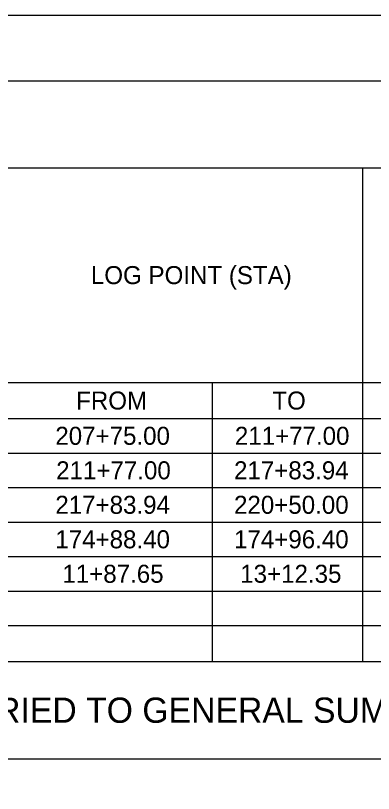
# Model space of a CAD drawing. Extents: x 0 to 53.1, y -5.3 to 22.
# Drawn here: x 5.19 to 7.93, y 16.05 to 22 of the extents above; entities that cross this region are included whole.
import ezdxf

# ---------------------------------------------------------------- set-up
doc = ezdxf.new("R2010")
doc.units = 0
for name, color, linetype in [('SH_Border', 7, 'Continuous'), ('SH_Cut_Line', 7, 'Continuous'), ('SH_Text', 7, 'Continuous')]:
    doc.layers.add(name, color=color, linetype=linetype)

msp = doc.modelspace()

# ---------------------------------------------------------------- linework, layer by layer
at = {"layer": 'SH_Border'}
msp.add_lwpolyline([(1.5, 21.5), (33.5, 21.5), (33.5, 0.5), (1.5, 0.5)], close=True, dxfattribs=at)
at = {"layer": 'SH_Cut_Line'}
msp.add_lwpolyline([(0, 0), (34, 0), (34, 22), (0, 22)], close=True, dxfattribs=at)
at = {"layer": 'SH_Text'}
for p, q in [((1.8384, 20.8354), (7.8504, 20.8354)), ((7.8504, 20.8354), (30.4824, 20.8354)), ((7.8504, 20.8354), (7.8504, 20.0194)), ((7.8504, 20.0194), (7.8504, 19.4674)), ((7.8504, 19.4674), (7.8504, 19.1914)), ((5.1144, 19.1914), (7.8504, 19.1914)), ((6.6984, 19.1914), (6.6984, 17.8594)), ((7.8504, 19.1914), (27.6024, 19.1914)), ((7.8504, 19.1914), (7.8504, 17.8594)), ((1.8384, 18.9154), (7.8504, 18.9154)), ((7.8504, 18.9154), (30.4824, 18.9154)), ((1.8384, 18.6514), (7.8504, 18.6514)), ((7.8504, 18.6514), (30.4824, 18.6514)), ((1.8384, 18.3874), (7.8504, 18.3874)), ((7.8504, 18.3874), (30.4824, 18.3874)), ((1.8384, 18.1234), (7.8504, 18.1234)), ((7.8504, 18.1234), (30.4824, 18.1234)), ((1.8384, 17.8594), (7.8504, 17.8594)), ((6.6984, 17.8594), (6.6984, 17.5954)), ((7.8504, 17.8594), (30.4824, 17.8594)), ((7.8504, 17.8594), (7.8504, 17.5954)), ((1.8384, 17.5954), (7.8504, 17.5954)), ((6.6984, 17.5954), (6.6984, 17.0554)), ((7.8504, 17.5954), (30.4824, 17.5954)), ((7.8504, 17.5954), (7.8504, 17.0554)), ((1.8384, 17.3314), (7.8504, 17.3314)), ((7.8504, 17.3314), (30.4824, 17.3314)), ((1.8384, 17.0554), (7.8504, 17.0554)), ((7.8504, 17.0554), (30.4824, 17.0554)), ((1.8384, 16.3114), (7.8504, 16.3114)), ((7.8504, 16.3114), (30.4824, 16.3114))]:
    msp.add_line(p, q, dxfattribs=at)

# ---------------------------------------------------------------- texts
for s, height, p in [('LOG POINT (STA)', 0.138, (5.7704, 19.9444)), ('FROM', 0.138, (5.6575, 18.9844)), ('TO', 0.138, (7.1593, 18.9844)), ('207+75.00', 0.138, (5.4982, 18.7144)), ('211+77.00', 0.138, (6.8726, 18.7144)), ('211+77.00', 0.138, (5.5046, 18.4504)), ('217+83.94', 0.138, (6.8662, 18.4504)), ('217+83.94', 0.138, (5.4982, 18.1864)), ('220+50.00', 0.138, (6.8662, 18.1864)), ('174+88.40', 0.138, (5.4982, 17.9224)), ('174+96.40', 0.138, (6.8662, 17.9224)), ('11+87.65', 0.138, (5.5522, 17.6584)), ('13+12.35', 0.138, (6.9137, 17.6584)), ('TOTALS CARRIED TO GENERAL SUMMARY', 0.1932, (3.4224, 16.5868))]:
    msp.add_text(s, height=height, dxfattribs=at).set_placement(p)

doc.saveas('drawing.dxf')
